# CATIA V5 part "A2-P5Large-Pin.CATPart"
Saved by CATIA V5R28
Part number: Large-Pin
Revision: ANY
Definition: UNKNOWN
Nomenclature: Large-Pin
Source: Unknown
Bounding box of the stored display mesh (mm): x -12.31 to 12.31, y -39 to 39, z -12.5 to 12.5
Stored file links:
  E:\TP Catia - Documents\Additional Exercise\Contrôle\Problem-3-Section-J\A2-P5Large-Pin.CATPart
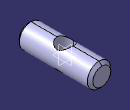
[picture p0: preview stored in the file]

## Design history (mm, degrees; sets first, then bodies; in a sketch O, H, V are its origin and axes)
Body1 "Imported1" (main body)
  Solid1: solid without history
